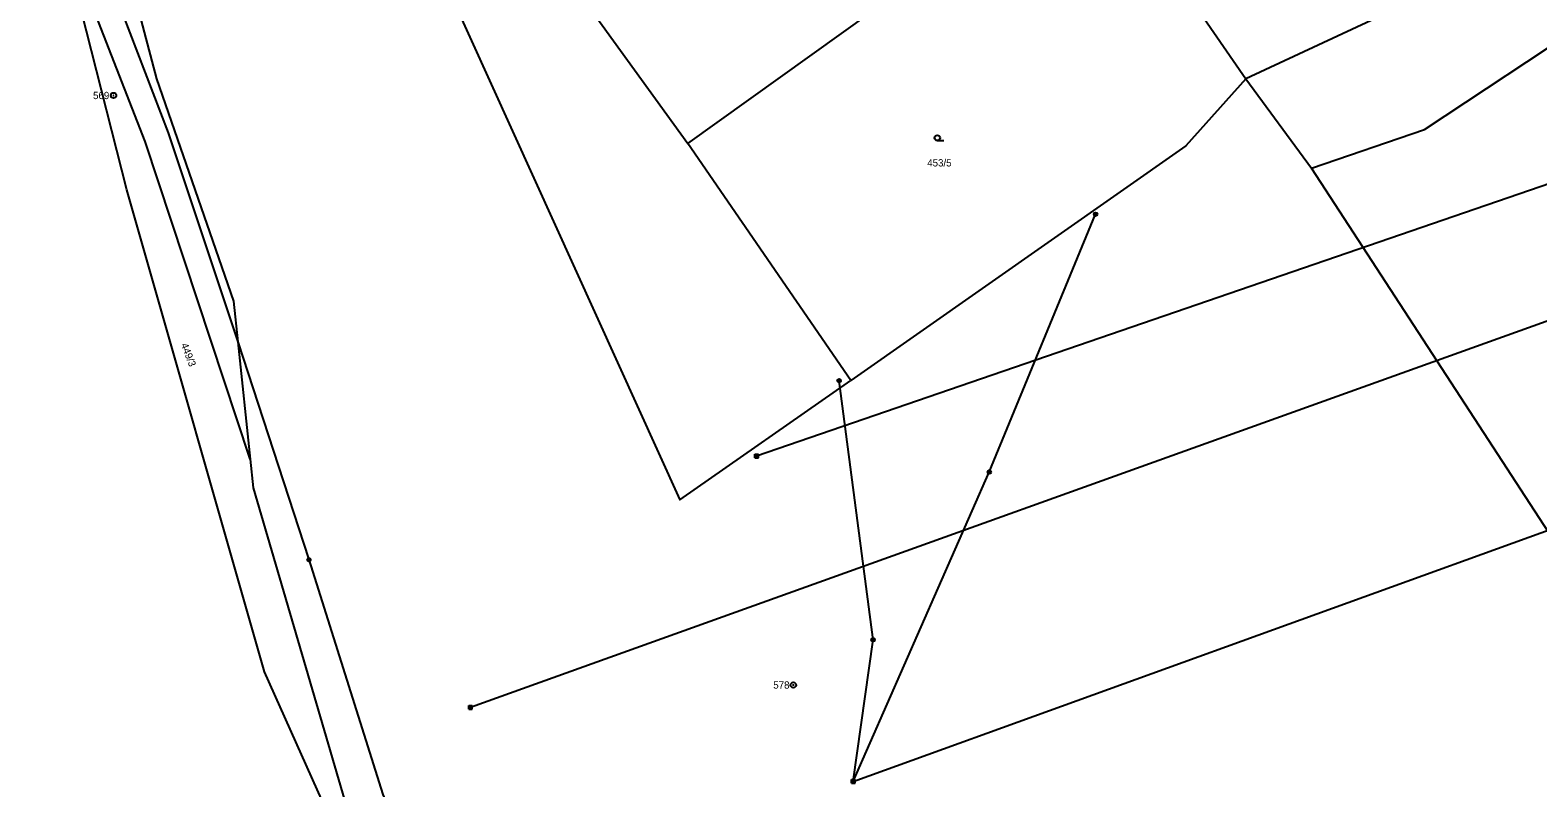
# Model space of a CAD drawing. Extents: x -745926 to -742978, y -968282 to -965689.
# Drawn here: x -745591.7 to -745384.4, y -966414.8 to -966310.5 of the extents above; entities that cross this region are included whole.
import ezdxf

# ---------------------------------------------------------------- set-up
doc = ezdxf.new("R2010")
doc.units = 0
for name, color, linetype in [('Hranice parcel', 7, 'Continuous'), ('Parcelní čísla', 7, 'Continuous'), ('Poz předměty', 7, 'Continuous'), ('Vnitřní kresba', 7, 'Continuous'), ('Značky bodu BP', 7, 'Continuous'), ('Značky kultur', 7, 'Continuous')]:
    doc.layers.add(name, color=color, linetype=linetype)

msp = doc.modelspace()

# ---------------------------------------------------------------- linework, layer by layer
at = {"layer": 'Hranice parcel'}
for p, q in [((-745424.56, -966317.24), (-745415.51, -966329.51)), ((-745561.43, -966369.57), (-745575.88, -966325.85)), ((-745572.68, -966324.66), (-745563.14, -966353.41)), ((-745295.83, -966513.68), (-745415.51, -966329.51)), ((-745563.14, -966353.41), (-745553.34, -966383.39)), ((-745563.14, -966353.41), (-745561.43, -966369.57))]:
    msp.add_line(p, q, dxfattribs=at)
for points in [[(-745575.88, -966325.85), (-745584.39, -966303.95), (-745586.75, -966294.46), (-745588.09, -966282.58), (-745588.84, -966258.96), (-745586.43, -966222.92), (-745582.91, -966201.97), (-745579.02, -966191.2), (-745573.75, -966179.49), (-745564.21, -966164.06), (-745553.71, -966151.1)], [(-745579.95, -966204.03), (-745502.37, -966375.18), (-745478.86, -966358.72)], [(-745417.98, -966541.13), (-745464.1, -966512.91), (-745510.64, -966478.01), (-745539.89, -966442.57), (-745559.43, -966398.82), (-745578.4, -966332.5), (-745589.48, -966288.79), (-745591.67, -966262.2)], [(-745585.1, -966276.23), (-745574.31, -966317.22), (-745563.73, -966347.82), (-745563.14, -966353.41)], [(-745415.51, -966329.51), (-745399.99, -966324.19), (-745377.39, -966309.27), (-745360.32, -966294.53), (-745355.31, -966277.88)], [(-745584.74, -966282.23), (-745583.31, -966294.15), (-745581.11, -966302.58), (-745572.68, -966324.66)], [(-745478.86, -966358.72), (-745501.27, -966326.12), (-745467.37, -966301.81), (-745440.14, -966294.47), (-745439.57, -966295.38), (-745424.56, -966317.24)], [(-745400.39, -966303.71), (-745404.67, -966307.97), (-745424.56, -966317.24)], [(-745424.56, -966317.24), (-745432.8, -966326.46), (-745478.86, -966358.72)], [(-745561.43, -966369.57), (-745561.01, -966373.53), (-745545.65, -966426.02), (-745535.57, -966439.18)], [(-745553.34, -966383.39), (-745543.18, -966415.69), (-745537.8, -966428.38), (-745531.77, -966438.97), (-745523.67, -966451.1), (-745515.99, -966461.71), (-745507.88, -966469.88), (-745491.93, -966482.14), (-745466.74, -966500.28), (-745413.83, -966539.16), (-745404.52, -966546.4), (-745395.52, -966554.15), (-745387.96, -966561.57), (-745383.02, -966567.24), (-745373.7, -966579.86)]]:
    msp.add_lwpolyline(points, dxfattribs=at)
at = {"layer": 'Poz předměty'}
for p, q in [((-745491.8, -966369.11), (-745334.1, -966314.82)), ((-745312.76, -966325.28), (-745531.13, -966403.73)), ((-745459.81, -966371.35), (-745445.2, -966335.86)), ((-745478.51, -966413.9), (-745316.74, -966355.38)), ((-745475.78, -966394.42), (-745480.46, -966358.77)), ((-745492.05, -966368.86), (-745491.55, -966368.86)), ((-745492.05, -966369.36), (-745492.05, -966368.86)), ((-745492.05, -966368.96), (-745491.55, -966368.96)), ((-745492.05, -966369.06), (-745491.55, -966369.06)), ((-745492.05, -966369.16), (-745491.55, -966369.16)), ((-745492.05, -966369.26), (-745491.55, -966369.26)), ((-745492.05, -966369.36), (-745491.55, -966369.36)), ((-745491.95, -966369.36), (-745491.95, -966368.86)), ((-745491.85, -966369.36), (-745491.85, -966368.86)), ((-745491.75, -966369.36), (-745491.75, -966368.86)), ((-745491.65, -966369.36), (-745491.65, -966368.86)), ((-745491.55, -966369.36), (-745491.55, -966368.86)), ((-745478.51, -966413.9), (-745459.81, -966371.35)), ((-745478.51, -966413.9), (-745475.78, -966394.42)), ((-745531.38, -966403.48), (-745530.88, -966403.48)), ((-745531.38, -966403.98), (-745531.38, -966403.48)), ((-745531.38, -966403.58), (-745530.88, -966403.58)), ((-745531.38, -966403.68), (-745530.88, -966403.68)), ((-745531.38, -966403.78), (-745530.88, -966403.78)), ((-745531.38, -966403.88), (-745530.88, -966403.88)), ((-745531.38, -966403.98), (-745530.88, -966403.98)), ((-745531.28, -966403.98), (-745531.28, -966403.48)), ((-745531.18, -966403.98), (-745531.18, -966403.48)), ((-745531.08, -966403.98), (-745531.08, -966403.48)), ((-745530.98, -966403.98), (-745530.98, -966403.48)), ((-745530.88, -966403.98), (-745530.88, -966403.48)), ((-745478.76, -966413.65), (-745478.26, -966413.65)), ((-745478.76, -966414.15), (-745478.76, -966413.65)), ((-745478.76, -966413.75), (-745478.26, -966413.75)), ((-745478.76, -966413.85), (-745478.26, -966413.85)), ((-745478.76, -966413.95), (-745478.26, -966413.95)), ((-745478.76, -966414.05), (-745478.26, -966414.05)), ((-745478.76, -966414.15), (-745478.26, -966414.15)), ((-745478.66, -966414.15), (-745478.66, -966413.65)), ((-745478.56, -966414.15), (-745478.56, -966413.65)), ((-745478.46, -966414.15), (-745478.46, -966413.65)), ((-745478.36, -966414.15), (-745478.36, -966413.65)), ((-745478.26, -966414.15), (-745478.26, -966413.65))]:
    msp.add_line(p, q, dxfattribs=at)
for centre, radius in [((-745445.2, -966335.86), 0.25), ((-745445.2, -966335.86), 0.2), ((-745445.2, -966335.86), 0.15), ((-745445.2, -966335.86), 0.1), ((-745445.2, -966335.86), 0.05), ((-745480.46, -966358.77), 0.25), ((-745480.46, -966358.77), 0.2), ((-745480.46, -966358.77), 0.15), ((-745480.46, -966358.77), 0.1), ((-745480.46, -966358.77), 0.05), ((-745459.81, -966371.35), 0.25), ((-745459.81, -966371.35), 0.2), ((-745459.81, -966371.35), 0.15), ((-745459.81, -966371.35), 0.1), ((-745459.81, -966371.35), 0.05), ((-745475.78, -966394.42), 0.25), ((-745475.78, -966394.42), 0.2), ((-745475.78, -966394.42), 0.15), ((-745475.78, -966394.42), 0.1), ((-745475.78, -966394.42), 0.05)]:
    msp.add_circle(centre, radius, dxfattribs=at)
at = {"layer": 'Vnitřní kresba'}
msp.add_line((-745530.25, -966286.04), (-745501.27, -966326.12), dxfattribs=at)
at = {"layer": 'Značky bodu BP'}
for centre, radius in [((-745580.2, -966319.52), 0.375), ((-745580.2, -966319.52), 0.015), ((-745553.34, -966383.39), 0.25), ((-745553.34, -966383.39), 0.0152), ((-745486.75, -966400.64), 0.375), ((-745486.75, -966400.64), 0.015)]:
    msp.add_circle(centre, radius, dxfattribs=at)
at = {"layer": 'Značky kultur'}
msp.add_line((-745466.96, -966325.74), (-745466.08, -966325.74), dxfattribs=at)
msp.add_circle((-745466.96, -966325.36), 0.375, dxfattribs=at)

# ---------------------------------------------------------------- texts
at = {"layer": 'Parcelní čísla'}
msp.add_text('453/5', height=1, dxfattribs=at).set_placement((-745468.34, -966329.29))
msp.add_text('449/3', height=1, rotation=291, dxfattribs=at).set_placement((-745570.96, -966353.81))
at = {"layer": 'Značky bodu BP'}
for s, p in [('569', (-745583.02, -966320.02)), ('578', (-745489.51, -966401.14))]:
    msp.add_text(s, height=1, dxfattribs=at).set_placement(p)

doc.saveas('drawing.dxf')
